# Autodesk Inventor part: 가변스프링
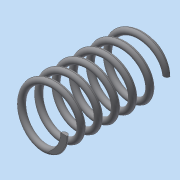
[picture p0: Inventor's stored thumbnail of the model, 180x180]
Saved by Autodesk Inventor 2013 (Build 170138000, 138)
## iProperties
Created: 2018-07
Part Number: 가변스프링
Material: 일반
Document SubType Name: Modeling
Designer: dgall
Density: 1 g/cm^3
Author: dgall
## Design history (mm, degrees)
sketch "스케치1"
  geometry: L1 (0, 0)-(0, 32.5); L2 (0, 0)-(8, 0); L3 (0, 32.5)-(8, 32.5); C1 r 1 at (8, 0)
  constraints: 6 end point, 1 centre point, 1 coincident, 1 parallel, 1 perpendicular, 1 vertical
  dimensions: "d0" = 32.5 distance of L1.start L1.end (derived); "d1" = 16 diameter of L2.end L1; "d2" = 16 diameter of L3.end L1; "d3" = 2 diameter of C1
feature "코일1" pitch "d4" = 10; turns "d6" = 6; dims "d5" = 32.5 (= d0), "d7" = 0, angle "d8" = 90 deg, angle "d9" = 90 deg, "d10" = 0, "d11" = 0
node "작업 평면1"
feature "분할1"
node "작업 평면2"
feature "분할2"
node "솔리드1"
other parameters: "d12" = 0, "d13" = 0
